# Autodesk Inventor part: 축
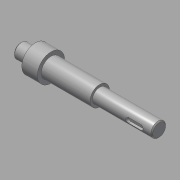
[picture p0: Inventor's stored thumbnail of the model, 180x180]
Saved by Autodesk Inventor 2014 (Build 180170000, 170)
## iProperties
Created: 2015-09
Part Number: 축
Material: 강철, 연강
Document SubType Name: Modeling
Designer: mduedu
Density: 7.86 g/cm^3
Mass: 263.424 g
Surface Area: 86.4309 cm^2
Volume: 33.5145 cm^3
Appearance: 강철
Author: mduedu
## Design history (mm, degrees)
sketch "스케치1"
  geometry: L1 (-71, 0)-(71, 0); L2 (-71, 0)-(-71, 7.5); L3 (-71, 7.5)-(-56, 7.5); L4 (-56, 7.5)-(-56, 14); L5 (-56, 14)-(-40, 14); L6 (-40, 14)-(-40, 10); L7 (-40, 10)-(10, 10); L8 (10, 10)-(10, 7.5); L9 (10, 7.5)-(71, 7.5); L10 (71, 7.5)-(71, 0); 2 further points
  constraints: 20 end point, 5 parallel, 2 horizontal, 2 perpendicular, 1 coincident, 1 midpoint, 1 vertical
  dimensions: "d0" = 142 distance of L1.start L1.end; "d2" = 16 distance of L4.end L5.end; "d3" = 50 distance of L6.end L7.end; "d5" = 15 diameter of L3 L1; "d6" = 15 diameter of L9 L1; "d7" = 20 diameter of L7 L1; "d8" = 28 diameter of L5 L1; "d31" = 15 distance of L2.end L3.end
revolve "회전1" sketch "스케치1" stored, may be unused: angle "d9" = 90 deg
node "작업 평면1"
sketch "스케치2"
  geometry: L1 (6, 2.5)-(19, 2.5); L2 (19, -2.5)-(6, -2.5); L3 (6, 2.5)-(19, -2.5); L4 (19, 2.5)-(6, -2.5); L5 (30.5, -7.5)-(30.5, 7.5) reference; A1 r 2.5 centre (6, 0) between (6, 2.5) and (6, -2.5); A2 r 2.5 centre (19, 0) between (19, -2.5) and (19, 2.5); 2 further points
  constraints: 8 end point, 4 point on circle, 4 tangent, 2 centre point, 2 midpoint, 1 horizontal, 1 horizontal alignment, 1 parallel
  dimensions: "d10" = 18 dimension on A2 A1; "d12" = 9 distance edge to line of A2 L5; "d13" = 5 distance between parallel lines of L2 L1
extrude "돌출1" cut sketch "스케치2" distance "d14" = 3; taper "d15" = 0 deg
node "작업 평면2"
sketch "스케치4"
  geometry: L1 (3, -3)-(-13, -3); L2 (-13, 3)-(3, 3); L3 (-25, 10)-(-25, -10) reference; A1 r 3 centre (-13, 0) between (-13, 3) and (-13, -3); A2 r 3 centre (3, 0) between (3, -3) and (3, 3); 1 further point
  constraints: 4 end point, 4 point on circle, 4 tangent, 2 centre point, 1 horizontal, 1 horizontal alignment, 1 parallel
  dimensions: "d16" = 22 dimension on A1 A2; "d18" = 6 distance between parallel lines of L2 L1; "d19" = 9 distance edge to line of A1 L3
extrude "돌출2" cut sketch "스케치4" distance "d20" = 3.5; taper "d21" = 0 deg
sketch "스케치5"
  geometry: L1 (10, 7.5)-(71, 7.5) reference; L2 (10, -7.5)-(71, -7.5) reference; L3 (45, 7.5)-(45, -7.5); L4 (45, -5.5)-(43, -7.5); L5 (45, -7.5)-(43, -7.5); L6 (45, -7.5)-(45, -5.5); L7 (10, -10)-(10, 10) reference; 1 further point
  constraints: 8 end point, 4 point on line, 1 collinear, 1 perpendicular
  dimensions: "d22" = 4 diameter of L4.end L3; "d24" = 45 deg angle of L3 L4; "d26" = 35 distance between parallel lines of L3 L7
revolve "회전2" sketch "스케치5" stored, may be unused: angle "d27" = 90 deg
chamfer "모따기1" distance "d28" = 1; stored, may be unused: second distance "d29" = 2, angle "d30" = 45 deg
sketch "스케치6"
  geometry: L1 (45, -5.5)-(43, -7.5) reference; L2 (45, -5.5)-(47, -7.5) reference; 2 further points
  constraints: 1 coincident
node "솔리드1"
